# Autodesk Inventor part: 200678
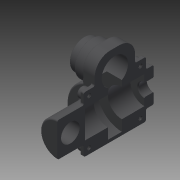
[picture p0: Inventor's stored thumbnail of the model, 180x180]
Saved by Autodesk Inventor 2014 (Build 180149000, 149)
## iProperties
Created: 2007-11
Part Number: 200678
Document SubType Name: Modeling
Designer: JJ
Density: 1.06 g/cm^3
Mass: 15.6401 g
Surface Area: 95.1366 cm^2
Volume: 14.7548 cm^3
Material: ABS Plastic
Description: GEAR HOUSING CASE SIDE 1
Appearance: Gray
Component Category: Lower Component
Author: JJ
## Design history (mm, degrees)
sketch "Sketch1"
  geometry: C1 r 11 at (0, 0); 1 further point
  constraints: 1 centre point, 1 coincident
  dimensions: "d0" = 22 diameter of C1
extrude "Extrusion1" new body sketch "Sketch1" distance "d1" = 62; taper "d2" = 0 deg
workplane "Work Plane1"
sketch "Sketch2"
  geometry: C1 r 11 at (0, 0) reference; C2 r 18 at (0, 0)
  constraints: 1 centre point, 1 coincident
  dimensions: "d4" = 36 diameter of C2
extrude "Extrusion2" join sketch "Sketch2" distance "d5" = 26; taper "d6" = 0 deg
sketch "Sketch3"
  geometry: L1 (50, -18)-(24, -18) reference; L2 (24, -18)-(24, -11) reference; L3 (24, -11)-(0, -11) reference; L4 (0, -11)-(0, 11) reference; L5 (0, 11)-(24, 11) reference; L6 (24, 11)-(24, 18) reference; L7 (24, 18)-(50, 18) reference; L8 (50, 18)-(50, 11) reference; L9 (50, 11)-(62, 11) reference; L10 (62, 11)-(62, -11) reference; L11 (62, -11)-(50, -11) reference; L12 (50, -11)-(50, -18) reference; L13 (0, 0)-(62, 0); L14 (24, 18)-(50, 18); L15 (50, 18)-(50, 33); L16 (50, 33)-(24, 33); L17 (24, 33)-(24, 18); L18 (24, 18)-(50, 18); L19 (50, 18)-(50, 14.5); L20 (50, 14.5)-(24, 14.5); L21 (24, 14.5)-(24, 18); L22 (56, 9.05)-(41.5, 9.05); L23 (17.85, 9.05)-(17.85, 0); L24 (62, 4.05)-(56, 4.05); L25 (56, 4.05)-(56, 9.05); L26 (32.5, 9.05)-(17.85, 9.05); L27 (41.5, 9.05)-(41.5, 16); L28 (32.5, 16)-(41.5, 16); L29 (32.5, 16)-(32.5, 9.05); L30 (17.85, 0)-(62, 0); L31 (62, 0)-(62, 4.05); C1 r 11 at (37, 20); C2 r 9.5 at (37, 20); C3 r 8.5 at (37, 20); C4 r 6 at (8.375, 0); 3 further points
  constraints: 38 end point, 5 midpoint, 5 parallel, 4 centre point, 4 perpendicular, 4 point on line, 2 coincident, 2 collinear, 2 horizontal, 1 vertical alignment, 1 other
  dimensions: "d7" = 22 diameter of C1; "d8" = 20 distance from line of C1.centre L13; "d9" = 15 distance of L14.end L15.end; "d10" = 13 distance from line of C1.centre L6; "d15" = 19 diameter of C2; "d16" = 17 diameter of C3; "d25" = 9.05 distance of L23.start L23.end; "d26" = 9 distance between parallel lines of L27 L29 (computed from d16); "d28" = 6 distance between parallel lines of L10 L25; "d29" = 4.05 distance between parallel lines of L30 L24; "d30" = 2 distance between parallel lines of L7 L28; "d31" = 14.65 distance between parallel lines of L29 L23; "d34" = 12 diameter of C4; "d35" = 8.37473 distance from line of L4 C4.centre (derived); "d67" = 26 distance of L15.end L16.end (derived); "d99" = 0.62527 distance of point (37.625, 20) C1.centre (derived)
  node "Project Cut Edges2"
extrude "Extrusion3" join sketch "Sketch3" stored distance "d11" = 16; taper "d12" = 0 deg
extrude "Extrusion4" join sketch "Sketch3" stored distance "d13" = 30; taper "d14" = 0 deg
extrude "Extrusion5" join sketch "Sketch3" stored distance "d17" = 40; taper "d18" = 0 deg
extrude "Extrusion6" cut sketch "Sketch3" stored distance "d19" = 34; taper "d20" = 0 deg
revolve "Revolution1" stored, may be unused: angle "d32" = 90 deg
split "Split1"
extrude "Extrusion7" cut sketch "Sketch3" stored distance "d36" = 56; taper "d37" = 0 deg
sketch "Sketch4"
  geometry: C1 r 9.5 at (0, 0) reference; C2 r 5 at (0, 0)
  constraints: 1 centre point, 1 coincident
  dimensions: "d40" = 10 diameter of C2
extrude "Extrusion8" cut sketch "Sketch4" stored distance "d41" = 56; taper "d42" = 0 deg
fillet "Fillet7" dims "d47" = 10
fillet "Fillet8" dims "d48" = 1
fillet "Fillet9" dims "d49" = 0.5
sketch "Sketch5"
  geometry: L1 (9, -13)-(-3, -13) reference; L2 (9, -13)-(2, -13); L3 (2, -13)-(2, -20); L4 (2, -20)-(9, -20); L5 (9, -20)-(9, -13); L6 (9, -20)-(11, -20); L7 (11, -20)-(11, -13); L8 (11, -13)-(9, -13); L9 (9, -13)-(9, -20); L10 (-13, -3)-(-13, 3) reference; L11 (-3, 13)-(9, 13) reference; L12 (-13, 0)-(-30.7, 0); L13 (20, -28.625)-(20, -23.982); L14 (9, 13)-(2, 13); L15 (2, 13)-(2, 20); L16 (2, 20)-(9, 20); L17 (9, 20)-(9, 13); L18 (11, 13)-(9, 13); L19 (9, 20)-(11, 20); L20 (11, 20)-(11, 13); L21 (9, 13)-(9, 20); L22 (31, -13)-(38, -13); L23 (38, -13)-(38, -20); L24 (38, -20)-(31, -20); L25 (31, -20)-(31, -13); L26 (31, -20)-(29, -20); L27 (29, -20)-(29, -13); L28 (29, -13)-(31, -13); L29 (31, -13)-(31, -20); L30 (31, 20)-(31, 13); L31 (31, 13)-(31, 20); L32 (29, 20)-(29, 13); L33 (31, 20)-(29, 20); L34 (38, 20)-(31, 20); L35 (38, 13)-(38, 20); L36 (31, 13)-(38, 13); L37 (29, 13)-(31, 13); C1 r 6 at (20, -28.625) reference; C2 r 3.25 at (34.5, -16.5); C3 r 3.25 at (34.5, 16.5); C4 r 3.25 at (5.5, 16.5); C5 r 3.25 at (5.5, -16.5); 7 further points
  constraints: 68 end point, 25 symmetric about line, 5 parallel, 4 centre point, 4 coincident, 3 perpendicular, 2 horizontal, 1 midpoint, 1 point on line
  dimensions: "d51" = 7 distance between parallel lines of L2 L4 (= d52); "d52" = 7 distance of L3.end L4.end; "d53" = 3.5 distance from line of L4 point (5.5, -16.5) (= 0.5 x d51); "d54" = 3.5 distance from line of L3 point (5.5, -16.5) (= 0.5 x d52); "d78" = 6.5 diameter of C2; "d79" = 6.5 diameter of C3 (= d78); "d80" = 6.5 diameter of C4 (= d78); "d81" = 6.5 diameter of C5 (= d78); "d91" = 2 distance between parallel lines of L9 L7
extrude "Extrusion9" join sketch "Sketch5" distance "d56" = 2; taper "d57" = 0 deg
extrude "Extrusion11" join sketch "Sketch5" distance "d82" = 5; taper "d83" = 0 deg
hole "Hole2" sketch "Sketch5" diameter "d84" = 2.459; stored, may be unused: countersink angle "d88" = 90 deg, drill point angle "d90" = 118 deg; dims "d85" = 6, "d86" = 6.3, "d87" = 2, "d89" = 4
chamfer "Chamfer1" distance "d92" = 0.5; stored, may be unused: second distance "d93" = 2, angle "d94" = 45 deg
fillet "Fillet13" dims "d95" = 1
fillet "Fillet14" dims "d96" = 1
fillet "Fillet15" dims "d97" = 1
fillet "Fillet16" dims "d98" = 1
body "Solid1"
node "Project Cut Edges1"
other parameters: "d3" = -24
